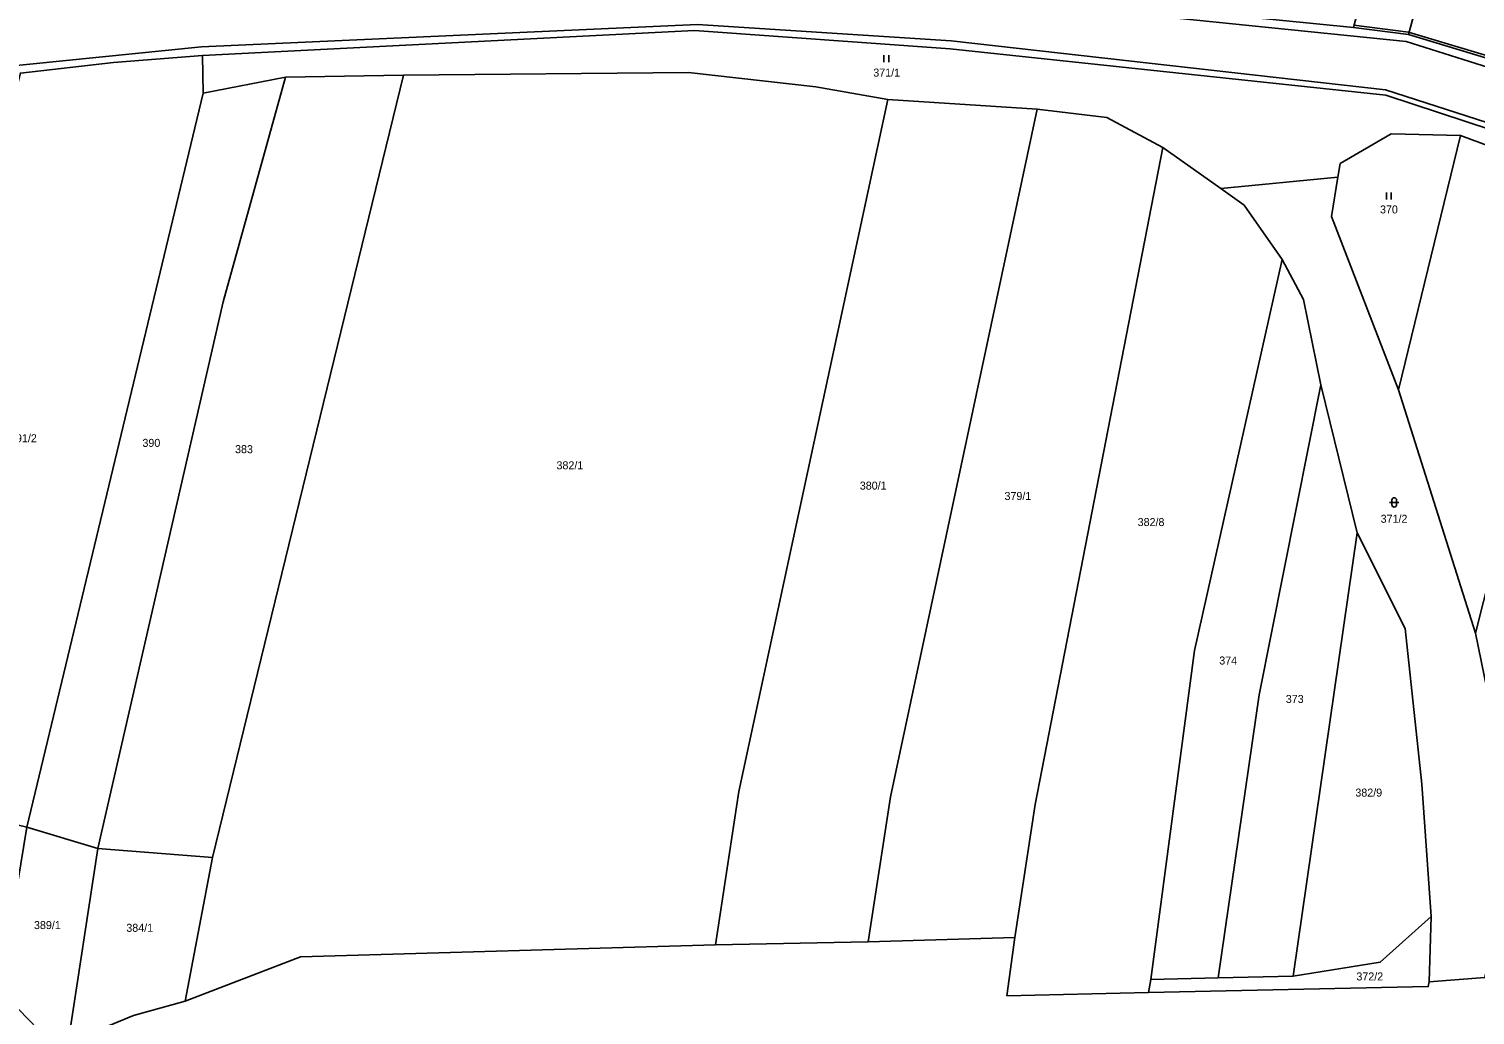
# Model space of a CAD drawing. Extents: x -654083 to -650132, y -1099819 to -1096699.
# Drawn here: x -652058 to -651750.7, y -1098221.2 to -1098011.7 of the extents above; entities that cross this region are included whole.
import ezdxf

# ---------------------------------------------------------------- set-up
doc = ezdxf.new("R2010")
doc.units = 0
for name, color, linetype in [('Hranice - vnitř_ kresba', 7, 'Continuous'), ('Obvody jako plochy', 7, 'Continuous'), ('Ostatní hranice', 7, 'Continuous'), ('Parcelní čísla', 7, 'Continuous'), ('Značky kultur', 7, 'Continuous')]:
    doc.layers.add(name, color=color, linetype=linetype)

msp = doc.modelspace()

# ---------------------------------------------------------------- linework, layer by layer
at = {"layer": 'Hranice - vnitř_ kresba'}
for p, q in [((-651765.35, -1098014.43), (-651839.14, -1098006.9)), ((-651915.96, -1098010.8), (-652021.29, -1098015.51)), ((-651915.96, -1098010.8), (-651862.05, -1098014.24)), ((-652090.52, -1098022.51), (-652021.29, -1098015.51)), ((-651862.05, -1098014.24), (-651769.76, -1098024.67)), ((-651698.5, -1098035.62), (-651765.35, -1098014.43)), ((-651769.76, -1098024.67), (-651690.25, -1098050.3))]:
    msp.add_line(p, q, dxfattribs=at)
at = {"layer": 'Obvody jako plochy'}
for points in [[(-651735.56, -1097905.42), (-651764.85, -1098012.89), (-651776.58, -1098011.42), (-651747.12, -1097898.87)], [(-651717.8, -1098002.3), (-651724.17, -1098025.21), (-651764.85, -1098012.89), (-651735.56, -1097905.42), (-651721.48, -1097913.27), (-651695.7, -1097934), (-651712.8, -1097983.39)], [(-651828.96, -1098030.53), (-651843.75, -1098028.78), (-651875.53, -1098026.69), (-651890.77, -1098024.05), (-651917.84, -1098021.01), (-651978.37, -1098021.57), (-652003.46, -1098021.95), (-652020.94, -1098025.36), (-652021.07, -1098017.35), (-651916.54, -1098012.04), (-651862.24, -1098015.94), (-651769.72, -1098025.77), (-651690.94, -1098051.72), (-651701.89, -1098050.1), (-651726.49, -1098044.5), (-651753.82, -1098034.34), (-651768.58, -1098034.03), (-651779.41, -1098040.34), (-651779.88, -1098043.19), (-651804.75, -1098045.64), (-651817.08, -1098036.9)], [(-652021.07, -1098017.35), (-652020.94, -1098025.36), (-652058.45, -1098181.32), (-652072.02, -1098178.04), (-652098.48, -1098173.49), (-652059.78, -1098021.1), (-652040.03, -1098018.88)], [(-652016.68, -1098069.68), (-652043.35, -1098185.84), (-652058.45, -1098181.32), (-652020.94, -1098025.36), (-652003.46, -1098021.95)], [(-652003.46, -1098021.95), (-651978.37, -1098021.57), (-652018.99, -1098187.76), (-652043.35, -1098185.84), (-652016.68, -1098069.68)], [(-652000.25, -1098208.86), (-651912.12, -1098206.3), (-651907.12, -1098173.76), (-651875.53, -1098026.69), (-651890.77, -1098024.05), (-651917.84, -1098021.01), (-651978.37, -1098021.57), (-652018.99, -1098187.76), (-652024.76, -1098218.27)], [(-651874.9, -1098174.88), (-651843.75, -1098028.78), (-651875.53, -1098026.69), (-651907.12, -1098173.76), (-651912.12, -1098206.3), (-651879.7, -1098205.7)], [(-651844.21, -1098176.53), (-651817.08, -1098036.9), (-651828.96, -1098030.53), (-651843.75, -1098028.78), (-651874.9, -1098174.88), (-651879.7, -1098205.7), (-651848.55, -1098204.76)], [(-651753.82, -1098034.34), (-651767.03, -1098088.41), (-651781.25, -1098051.61), (-651779.88, -1098043.19), (-651779.41, -1098040.34), (-651768.58, -1098034.03)], [(-651726.49, -1098044.5), (-651750.66, -1098140.13), (-651767.03, -1098088.41), (-651753.82, -1098034.34)], [(-651819.65, -1098213.66), (-651820.1, -1098216.41), (-651850.21, -1098217.13), (-651848.55, -1098204.76), (-651844.21, -1098176.53), (-651817.08, -1098036.9), (-651804.75, -1098045.64), (-651799.8, -1098049.15), (-651791.74, -1098060.75), (-651810.38, -1098143.8)], [(-651760.47, -1098214.21), (-651748.65, -1098213.24), (-651742.11, -1098181.97), (-651750.66, -1098140.13), (-651767.03, -1098088.41), (-651781.25, -1098051.61), (-651779.88, -1098043.19), (-651804.75, -1098045.64), (-651799.8, -1098049.15), (-651791.74, -1098060.75), (-651787.17, -1098069.18), (-651783.47, -1098087.31), (-651775.77, -1098118.81), (-651765.56, -1098139.1), (-651762.04, -1098172.17), (-651760.03, -1098200.32)], [(-651796.58, -1098153.21), (-651805.34, -1098213.35), (-651819.65, -1098213.66), (-651810.38, -1098143.8), (-651791.74, -1098060.75), (-651787.17, -1098069.18), (-651783.47, -1098087.31)], [(-651783.47, -1098087.31), (-651775.77, -1098118.81), (-651789.37, -1098212.94), (-651805.34, -1098213.35), (-651796.58, -1098153.21)], [(-651775.77, -1098118.81), (-651765.56, -1098139.1), (-651762.04, -1098172.17), (-651760.03, -1098200.32), (-651770.88, -1098210.02), (-651789.37, -1098212.94)], [(-652043.35, -1098185.84), (-652049.67, -1098227.08), (-652052.14, -1098228.35), (-652064.08, -1098215.97), (-652058.45, -1098181.32)], [(-652043.35, -1098185.84), (-652018.99, -1098187.76), (-652024.76, -1098218.27), (-652035.78, -1098221.33), (-652049.67, -1098227.08)], [(-651760.69, -1098215.2), (-651820.1, -1098216.41), (-651819.65, -1098213.66), (-651805.34, -1098213.35), (-651789.37, -1098212.94), (-651770.88, -1098210.02), (-651760.03, -1098200.32), (-651760.47, -1098214.21)]]:
    msp.add_lwpolyline(points, close=True, dxfattribs=at)
for points in [[(-651724.17, -1098025.21), (-651764.85, -1098012.89), (-651776.58, -1098011.42), (-651807.29, -1098008.38), (-651838.62, -1098005.35), (-651854.81, -1098003.68), (-651868.71, -1098002.6), (-651895, -1098000.62), (-651916.35, -1097999.47), (-651979.22, -1098002.36), (-651991.34, -1098002.89), (-652003.07, -1098003.7), (-652012.04, -1098004.16), (-652017.6, -1098004.37), (-652090.85, -1098009.1)], [(-652059.78, -1098021.1), (-652040.03, -1098018.88), (-652021.07, -1098017.35), (-651916.54, -1098012.04), (-651862.24, -1098015.94), (-651769.72, -1098025.77), (-651690.94, -1098051.72)], [(-652064.08, -1098215.97), (-652052.14, -1098228.35), (-652049.67, -1098227.08), (-652035.78, -1098221.33), (-652024.76, -1098218.27), (-652000.25, -1098208.86), (-651912.12, -1098206.3), (-651879.7, -1098205.7), (-651848.55, -1098204.76), (-651850.21, -1098217.13), (-651820.1, -1098216.41), (-651760.69, -1098215.2), (-651760.47, -1098214.21), (-651748.65, -1098213.24)]]:
    msp.add_lwpolyline(points, dxfattribs=at)
at = {"layer": 'Ostatní hranice'}
for q in [(-651776.52, -1098010.92), (-651724.03, -1098024.73)]:
    msp.add_line((-651764.91, -1098012.39), q, dxfattribs=at)
at = {"layer": 'Značky kultur'}
for p, q in [((-651876.32, -1098017.28), (-651876.32, -1098018.78)), ((-651875.3, -1098018.78), (-651875.3, -1098017.28)), ((-651769.56, -1098046.5), (-651769.56, -1098048)), ((-651768.54, -1098048), (-651768.54, -1098046.5)), ((-651768.4, -1098112.82), (-651768.4, -1098111.82)), ((-651767.4, -1098112.82), (-651767.4, -1098111.82)), ((-651768.9, -1098112.32), (-651766.9, -1098112.32))]:
    msp.add_line(p, q, dxfattribs=at)
for centre, start, end in [((-651767.9, -1098111.82), 0, 180), ((-651767.9, -1098112.82), 180, 0)]:
    msp.add_arc(centre, 0.5, start, end, dxfattribs=at)

# ---------------------------------------------------------------- texts
at = {"layer": 'Parcelní čísla'}
for s, p in [('371/1', (-651878.59, -1098021.86)), ('370', (-651770.93, -1098050.93)), ('391/2', (-652061.99, -1098099.54)), ('390', (-652033.86, -1098100.52)), ('383', (-652014.18, -1098101.86)), ('382/1', (-651945.89, -1098105.29)), ('380/1', (-651881.45, -1098109.6)), ('379/1', (-651850.71, -1098111.81)), ('371/2', (-651770.8, -1098116.65)), ('382/8', (-651822.42, -1098117.35)), ('374', (-651805.08, -1098146.76)), ('373', (-651790.95, -1098154.93)), ('382/9', (-651776.17, -1098174.82)), ('389/1', (-652056.9, -1098202.97)), ('384/1', (-652037.28, -1098203.55)), ('372/2', (-651775.95, -1098213.88))]:
    msp.add_text(s, height=1.7, dxfattribs=at).set_placement(p)

doc.saveas('drawing.dxf')
